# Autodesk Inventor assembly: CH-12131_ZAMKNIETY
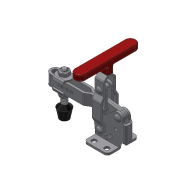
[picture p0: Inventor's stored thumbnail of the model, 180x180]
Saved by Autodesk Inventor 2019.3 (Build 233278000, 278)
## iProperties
Company: Î¢ÈíÖÐ¹ú
Created: 2012-09
Part Number: CH-12131_ZAMKNIETY
Material: Ogólny
Description: STEP AP203
Document SubType Name: Assembly
Designer: CADENGINEERING4
Sending System: SolidWorks 2010
Preprocessor: SwSTEP 2.0
Title: CH-12131.STEP
Author: Î¢ÈíÓÃ»§
Revision Number: ÈÎºÎ
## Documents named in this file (11)
- D:\Vault_2016\Projekty\NASZ KATALOG\CLAMPTEK\STRONA\Vertical toggle clamp\CH-12131\CH-12131_ZAMKNIETY.iam
- D:\Vault_2016\Projekty\NASZ KATALOG\CLAMPTEK\STEP FILES\Vertical toggle clamp\CH-12131\CH-FW-516.ipt
- D:\Vault_2016\Projekty\NASZ KATALOG\CLAMPTEK\STEP FILES\Vertical toggle clamp\CH-12131\CH-FC-56212 Nut.ipt
- D:\Vault_2016\Projekty\NASZ KATALOG\CLAMPTEK\STEP FILES\Vertical toggle clamp\CH-12131\CH-12130-06.ipt
- D:\Vault_2016\Projekty\NASZ KATALOG\CLAMPTEK\STEP FILES\Vertical toggle clamp\CH-12131\CH-12148-03 T-HANDLE.ipt
- D:\Vault_2016\Projekty\NASZ KATALOG\CLAMPTEK\STEP FILES\Vertical toggle clamp\CH-12131\CH-FC-56212 SPINDLE SUPPLIED.ipt
- D:\Vault_2016\Projekty\NASZ KATALOG\CLAMPTEK\STEP FILES\Vertical toggle clamp\CH-12131\CH-12130-01 FLANGED BASE.ipt
- D:\Vault_2016\Projekty\NASZ KATALOG\CLAMPTEK\STEP FILES\Vertical toggle clamp\CH-12131\CH-12130-04 CONNECTING-PLATE.ipt
- D:\Vault_2016\Projekty\NASZ KATALOG\CLAMPTEK\STEP FILES\Vertical toggle clamp\CH-12131\CH-12131-02 SHORT U-BAR.ipt
- D:\Vault_2016\Projekty\NASZ KATALOG\CLAMPTEK\STEP FILES\Vertical toggle clamp\CH-12131\CH-12130-08.ipt
- D:\Vault_2016\Projekty\NASZ KATALOG\CLAMPTEK\STEP FILES\Vertical toggle clamp\CH-12131\CH-12130-05.ipt
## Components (14 placed, 14 different names)
1. CH-FW-516_1
2. CH-FC-56212 Nut_2
3. CH-12130-06_3
4. CH-12130-06_4
5. CH-12148-03 T-HANDLE_5
6. CH-FC-56212 Nut_6
7. CH-FC-56212 SPINDLE SUPPLIED_7
8. CH-FW-516_8
9. CH-12130-01 FLANGED BASE_9
10. CH-12130-04 CONNECTING-PLATE_10
11. CH-12131-02 SHORT U-BAR_11
12. CH-12130-08_12
13. CH-12130-08_13
14. CH-12130-05_14
